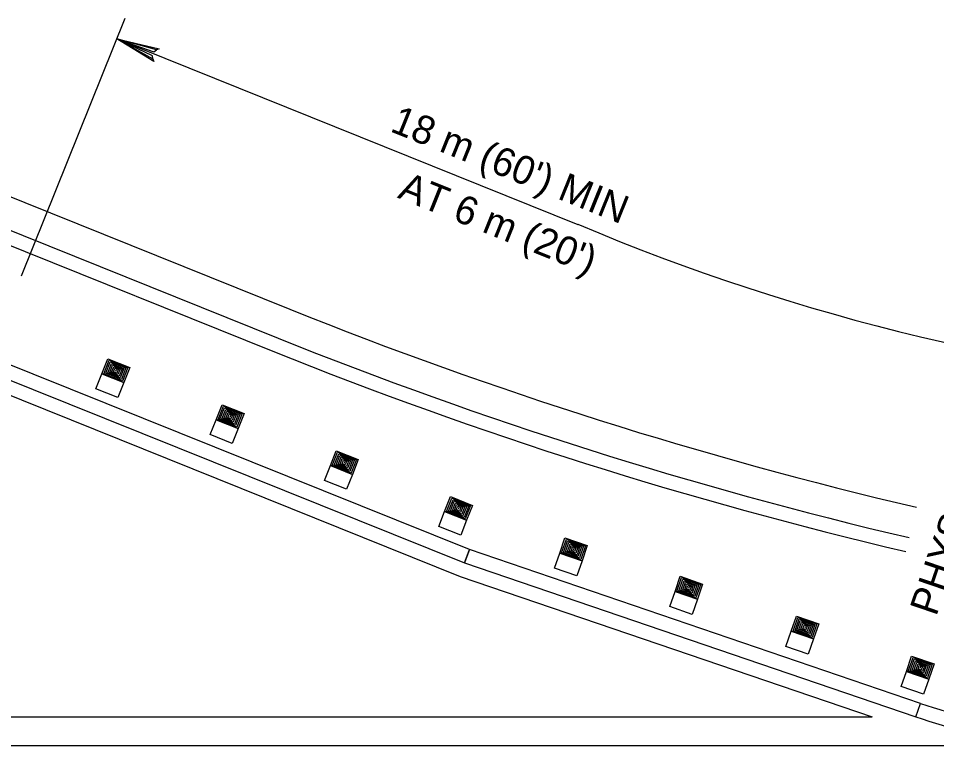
# Model space of a CAD drawing. Extents: x 639362 to 641108, y 298458 to 299646.
# Drawn here: x 639554.2 to 639651.2, y 299503.7 to 299580.5 of the extents above; entities that cross this region are included whole.
import ezdxf

# ---------------------------------------------------------------- set-up
doc = ezdxf.new("R2010")
doc.units = 0
doc.layers.add('2', color=7, linetype='Continuous')

msp = doc.modelspace()

# ---------------------------------------------------------------- linework, layer by layer
at = {"layer": '2'}
for p, q in [((639565.5, 299580.517), (639554.544, 299553.298)), ((639564.624, 299578.342), (639613.294, 299558.754)), ((639520.274, 299575.006), (639582.89, 299549.802)), ((639519.042, 299571.944), (639581.658, 299546.74)), ((639518.53, 299570.534), (639581.098, 299545.349)), ((639601.865, 299524.396), (639514.528, 299559.549)), ((639613.294, 299558.754), (639613.301, 299558.772)), ((639514.014, 299558.139), (639601.342, 299522.99)), ((639513.561, 299556.709), (639600.897, 299521.557)), ((639563.06, 299542.974), (639563.684, 299544.552)), ((639563.261, 299542.98), (639563.825, 299544.405)), ((639563.47, 299543.02), (639563.95, 299544.234)), ((639563.676, 299543.061), (639564.073, 299544.062)), ((639563.684, 299544.552), (639566.008, 299543.632)), ((639563.825, 299544.405), (639565.804, 299543.622)), ((639563.884, 299543.101), (639564.197, 299543.892)), ((639563.95, 299544.234), (639565.601, 299543.581)), ((639564.073, 299544.062), (639565.393, 299543.54)), ((639564.197, 299543.892), (639565.187, 299543.5)), ((639565.383, 299542.054), (639563.06, 299542.974)), ((639565.241, 299542.197), (639563.261, 299542.98)), ((639565.12, 299542.367), (639563.47, 299543.02)), ((639564.996, 299542.538), (639563.676, 299543.061)), ((639564.874, 299542.709), (639563.884, 299543.101)), ((639564.09, 299543.141), (639564.32, 299543.721)), ((639564.75, 299542.88), (639564.09, 299543.141)), ((639564.298, 299543.181), (639564.444, 299543.551)), ((639564.627, 299543.051), (639564.298, 299543.181)), ((639564.32, 299543.721), (639564.979, 299543.46)), ((639564.444, 299543.551), (639564.773, 299543.421)), ((639564.565, 299543.382), (639564.502, 299543.222)), ((639564.773, 299543.421), (639564.627, 299543.051)), ((639564.979, 299543.46), (639564.75, 299542.88)), ((639565.187, 299543.5), (639564.874, 299542.709)), ((639565.393, 299543.54), (639564.996, 299542.538)), ((639565.601, 299543.581), (639565.12, 299542.367)), ((639565.804, 299543.622), (639565.241, 299542.197)), ((639566.008, 299543.632), (639565.383, 299542.054)), ((639575.119, 299538.12), (639575.744, 299539.698)), ((639575.321, 299538.126), (639575.885, 299539.551)), ((639575.53, 299538.166), (639576.01, 299539.38)), ((639575.736, 299538.206), (639576.133, 299539.208)), ((639575.744, 299539.698), (639578.067, 299538.778)), ((639575.885, 299539.551), (639577.864, 299538.768)), ((639575.944, 299538.247), (639576.257, 299539.037)), ((639576.01, 299539.38), (639577.66, 299538.726)), ((639576.133, 299539.208), (639577.453, 299538.686)), ((639576.257, 299539.037), (639577.247, 299538.646)), ((639577.443, 299537.2), (639575.119, 299538.12)), ((639577.3, 299537.343), (639575.321, 299538.126)), ((639577.18, 299537.513), (639575.53, 299538.166)), ((639577.056, 299537.684), (639575.736, 299538.206)), ((639576.934, 299537.855), (639575.944, 299538.247)), ((639576.15, 299538.287), (639576.38, 299538.867)), ((639576.809, 299538.026), (639576.15, 299538.287)), ((639576.357, 299538.327), (639576.504, 299538.697)), ((639576.687, 299538.196), (639576.357, 299538.327)), ((639576.38, 299538.867), (639577.039, 299538.606)), ((639576.504, 299538.697), (639576.833, 299538.567)), ((639576.624, 299538.527), (639576.561, 299538.368)), ((639576.833, 299538.567), (639576.687, 299538.196)), ((639577.039, 299538.606), (639576.809, 299538.026)), ((639577.247, 299538.646), (639576.934, 299537.855)), ((639577.453, 299538.686), (639577.056, 299537.684)), ((639577.66, 299538.726), (639577.18, 299537.513)), ((639577.864, 299538.768), (639577.3, 299537.343)), ((639578.067, 299538.778), (639577.443, 299537.2)), ((639587.179, 299533.265), (639587.804, 299534.843)), ((639587.38, 299533.272), (639587.944, 299534.697)), ((639587.59, 299533.312), (639588.07, 299534.525)), ((639587.796, 299533.352), (639588.192, 299534.354)), ((639587.804, 299534.843), (639590.127, 299533.924)), ((639587.944, 299534.697), (639589.924, 299533.913)), ((639588.004, 299533.393), (639588.316, 299534.183)), ((639588.07, 299534.525), (639589.72, 299533.872)), ((639588.192, 299534.354), (639589.513, 299533.832)), ((639588.316, 299534.183), (639589.306, 299533.791)), ((639589.503, 299532.346), (639587.179, 299533.265)), ((639589.36, 299532.488), (639587.38, 299533.272)), ((639589.24, 299532.659), (639587.59, 299533.312)), ((639589.116, 299532.83), (639587.796, 299533.352)), ((639588.993, 299533.001), (639588.004, 299533.393)), ((639588.21, 299533.433), (639588.439, 299534.013)), ((639588.869, 299533.172), (639588.21, 299533.433)), ((639588.417, 299533.473), (639588.564, 299533.843)), ((639588.746, 299533.342), (639588.417, 299533.473)), ((639588.439, 299534.013), (639589.099, 299533.752)), ((639588.564, 299533.843), (639588.893, 299533.712)), ((639588.684, 299533.673), (639588.621, 299533.514)), ((639588.893, 299533.712), (639588.746, 299533.342)), ((639589.099, 299533.752), (639588.869, 299533.172)), ((639589.306, 299533.791), (639588.993, 299533.001)), ((639589.513, 299533.832), (639589.116, 299532.83)), ((639589.72, 299533.872), (639589.24, 299532.659)), ((639589.924, 299533.913), (639589.36, 299532.488)), ((639590.127, 299533.924), (639589.503, 299532.346)), ((639599.239, 299528.411), (639599.863, 299529.989)), ((639599.44, 299528.418), (639600.004, 299529.843)), ((639599.649, 299528.458), (639600.13, 299529.671)), ((639599.856, 299528.498), (639600.252, 299529.5)), ((639599.863, 299529.989), (639602.187, 299529.069)), ((639600.004, 299529.843), (639601.984, 299529.059)), ((639600.063, 299528.538), (639600.376, 299529.329)), ((639600.13, 299529.671), (639601.78, 299529.018)), ((639600.252, 299529.5), (639601.572, 299528.977)), ((639600.376, 299529.329), (639601.366, 299528.937)), ((639601.562, 299527.492), (639599.239, 299528.411)), ((639601.42, 299527.634), (639599.44, 299528.418)), ((639601.3, 299527.804), (639599.649, 299528.458)), ((639601.176, 299527.975), (639599.856, 299528.498)), ((639601.053, 299528.147), (639600.063, 299528.538)), ((639600.27, 299528.579), (639600.499, 299529.158)), ((639600.929, 299528.318), (639600.27, 299528.579)), ((639600.477, 299528.618), (639600.623, 299528.988)), ((639600.806, 299528.488), (639600.477, 299528.618)), ((639600.499, 299529.158), (639601.159, 299528.897)), ((639600.623, 299528.988), (639600.953, 299528.858)), ((639600.744, 299528.819), (639600.681, 299528.659)), ((639600.953, 299528.858), (639600.806, 299528.488)), ((639601.159, 299528.897), (639600.929, 299528.318)), ((639601.366, 299528.937), (639601.053, 299528.147)), ((639601.572, 299528.977), (639601.176, 299527.975)), ((639601.78, 299529.018), (639601.3, 299527.804)), ((639601.984, 299529.059), (639601.42, 299527.634)), ((639602.187, 299529.069), (639601.562, 299527.492)), ((639611.392, 299524.032), (639611.943, 299525.637)), ((639611.593, 299524.047), (639612.09, 299525.497)), ((639611.8, 299524.097), (639612.223, 299525.332)), ((639611.943, 299525.637), (639614.306, 299524.826)), ((639612.09, 299525.497), (639614.104, 299524.806)), ((639612.223, 299525.332), (639613.902, 299524.755)), ((639601.866, 299524.396), (639601.342, 299522.99)), ((639601.342, 299522.99), (639601.865, 299524.396)), ((639649.463, 299508.153), (639601.866, 299524.396)), ((639612.004, 299524.147), (639612.354, 299525.166)), ((639612.21, 299524.197), (639612.486, 299525.001)), ((639612.354, 299525.166), (639613.697, 299524.705)), ((639612.414, 299524.247), (639612.616, 299524.836)), ((639612.486, 299525.001), (639613.493, 299524.655)), ((639612.616, 299524.836), (639613.287, 299524.606)), ((639612.619, 299524.296), (639612.748, 299524.672)), ((639612.748, 299524.672), (639613.083, 299524.557)), ((639612.877, 299524.509), (639612.821, 299524.346)), ((639613.083, 299524.557), (639612.954, 299524.181)), ((639613.287, 299524.606), (639613.085, 299524.016)), ((639613.493, 299524.655), (639613.216, 299523.851)), ((639613.697, 299524.705), (639613.347, 299523.686)), ((639613.902, 299524.755), (639613.478, 299523.521)), ((639614.104, 299524.806), (639613.606, 299523.356)), ((639614.306, 299524.826), (639613.755, 299523.22)), ((639613.755, 299523.22), (639611.392, 299524.032)), ((639613.606, 299523.356), (639611.593, 299524.047)), ((639613.478, 299523.521), (639611.8, 299524.097)), ((639613.347, 299523.686), (639612.004, 299524.147)), ((639613.216, 299523.851), (639612.21, 299524.197)), ((639613.085, 299524.016), (639612.414, 299524.247)), ((639612.954, 299524.181), (639612.619, 299524.296)), ((639601.342, 299522.99), (639648.969, 299506.737)), ((639600.897, 299521.557), (639644.371, 299506.721)), ((639623.561, 299519.978), (639624.117, 299521.581)), ((639624.117, 299521.581), (639626.478, 299520.762)), ((639623.762, 299519.993), (639624.264, 299521.441)), ((639623.969, 299520.042), (639624.397, 299521.275)), ((639624.174, 299520.091), (639624.527, 299521.109)), ((639624.264, 299521.441), (639626.276, 299520.743)), ((639624.38, 299520.14), (639624.658, 299520.943)), ((639624.397, 299521.275), (639626.074, 299520.693)), ((639624.527, 299521.109), (639625.868, 299520.644)), ((639624.584, 299520.189), (639624.788, 299520.779)), ((639624.658, 299520.943), (639625.664, 299520.595)), ((639624.788, 299520.779), (639625.458, 299520.546)), ((639624.789, 299520.238), (639624.92, 299520.614)), ((639624.92, 299520.614), (639625.254, 299520.498)), ((639625.254, 299520.498), (639625.124, 299520.122)), ((639625.458, 299520.546), (639625.254, 299519.957)), ((639625.664, 299520.595), (639625.385, 299519.791)), ((639625.868, 299520.644), (639625.515, 299519.626)), ((639626.074, 299520.693), (639625.646, 299519.46)), ((639626.276, 299520.743), (639625.774, 299519.295)), ((639626.478, 299520.762), (639625.922, 299519.159)), ((639625.922, 299519.159), (639623.561, 299519.978)), ((639625.774, 299519.295), (639623.762, 299519.993)), ((639625.646, 299519.46), (639623.969, 299520.042)), ((639625.515, 299519.626), (639624.174, 299520.091)), ((639625.385, 299519.791), (639624.38, 299520.14)), ((639625.254, 299519.957), (639624.584, 299520.189)), ((639625.124, 299520.122), (639624.789, 299520.238)), ((639625.047, 299520.45), (639624.991, 299520.288)), ((639635.821, 299515.776), (639636.377, 299517.379)), ((639636.022, 299515.791), (639636.524, 299517.239)), ((639636.229, 299515.84), (639636.656, 299517.073)), ((639636.377, 299517.379), (639638.738, 299516.561)), ((639636.433, 299515.889), (639636.786, 299516.907)), ((639636.524, 299517.239), (639638.535, 299516.541)), ((639636.639, 299515.939), (639636.917, 299516.742)), ((639636.656, 299517.073), (639638.333, 299516.492)), ((639636.786, 299516.907), (639638.128, 299516.442)), ((639636.917, 299516.742), (639637.923, 299516.393)), ((639638.181, 299514.957), (639635.821, 299515.776)), ((639638.033, 299515.094), (639636.022, 299515.791)), ((639637.905, 299515.258), (639636.229, 299515.84)), ((639637.774, 299515.424), (639636.433, 299515.889)), ((639637.645, 299515.59), (639636.639, 299515.939)), ((639636.843, 299515.988), (639637.047, 299516.577)), ((639637.513, 299515.755), (639636.843, 299515.988)), ((639637.047, 299516.577), (639637.718, 299516.344)), ((639637.049, 299516.036), (639637.179, 299516.412)), ((639637.383, 299515.92), (639637.049, 299516.036)), ((639637.179, 299516.412), (639637.514, 299516.296)), ((639637.307, 299516.248), (639637.25, 299516.086)), ((639637.514, 299516.296), (639637.383, 299515.92)), ((639637.718, 299516.344), (639637.513, 299515.755)), ((639637.923, 299516.393), (639637.645, 299515.59)), ((639638.128, 299516.442), (639637.774, 299515.424)), ((639638.333, 299516.492), (639637.905, 299515.258)), ((639638.535, 299516.541), (639638.033, 299515.094)), ((639638.738, 299516.561), (639638.181, 299514.957)), ((639647.986, 299511.532), (639648.542, 299513.136)), ((639648.187, 299511.547), (639648.689, 299512.995)), ((639648.394, 299511.596), (639648.821, 299512.829)), ((639648.542, 299513.136), (639650.902, 299512.317)), ((639648.689, 299512.995), (639650.7, 299512.297)), ((639648.821, 299512.829), (639650.498, 299512.248)), ((639648.598, 299511.645), (639648.951, 299512.663)), ((639648.804, 299511.695), (639649.083, 299512.498)), ((639648.951, 299512.663), (639650.292, 299512.198)), ((639649.008, 299511.744), (639649.213, 299512.333)), ((639649.083, 299512.498), (639650.088, 299512.149)), ((639649.213, 299512.333), (639649.883, 299512.1)), ((639649.214, 299511.792), (639649.344, 299512.168)), ((639649.548, 299511.676), (639649.214, 299511.792)), ((639649.344, 299512.168), (639649.679, 299512.052)), ((639649.472, 299512.004), (639649.416, 299511.842)), ((639649.679, 299512.052), (639649.548, 299511.676)), ((639649.883, 299512.1), (639649.678, 299511.511)), ((639650.088, 299512.149), (639649.809, 299511.346)), ((639650.292, 299512.198), (639649.939, 299511.18)), ((639650.498, 299512.248), (639650.071, 299511.014)), ((639650.7, 299512.297), (639650.198, 299510.85)), ((639650.902, 299512.317), (639650.346, 299510.713)), ((639650.346, 299510.713), (639647.986, 299511.532)), ((639650.198, 299510.85), (639648.187, 299511.547)), ((639650.071, 299511.014), (639648.394, 299511.596)), ((639649.939, 299511.18), (639648.598, 299511.645)), ((639649.809, 299511.346), (639648.804, 299511.695)), ((639649.678, 299511.511), (639649.008, 299511.744)), ((639648.969, 299506.737), (639649.463, 299508.153)), ((639511.242, 299506.721), (639644.371, 299506.721)), ((639511.242, 299503.694), (639660.336, 299503.694))]:
    msp.add_line(p, q, dxfattribs=at)
msp.add_lwpolyline([(639568.428, 299576.226), (639568.391, 299576.575), (639564.624, 299578.342), (639568.428, 299576.226), (639568.56, 299575.967), (639564.624, 299578.342), (639568.555, 299576.982), (639568.811, 299577.209), (639564.624, 299578.342), (639569.101, 299577.314), (639568.811, 299577.209)], dxfattribs=at)
for points in [[(639563.06, 299542.974), (639565.383, 299542.054), (639564.759, 299540.476), (639562.435, 299541.396)], [(639575.119, 299538.119), (639577.443, 299537.2), (639576.818, 299535.622), (639574.495, 299536.541)], [(639587.179, 299533.265), (639589.503, 299532.346), (639588.878, 299530.768), (639586.555, 299531.687)], [(639599.239, 299528.411), (639601.562, 299527.491), (639600.938, 299525.913), (639598.614, 299526.833)], [(639611.392, 299524.032), (639613.755, 299523.22), (639613.204, 299521.615), (639610.841, 299522.426)], [(639623.561, 299519.978), (639625.922, 299519.159), (639625.366, 299517.555), (639623.005, 299518.374)], [(639635.821, 299515.776), (639638.181, 299514.957), (639637.625, 299513.354), (639635.264, 299514.173)], [(639647.986, 299511.532), (639650.346, 299510.713), (639649.79, 299509.11), (639647.43, 299509.928)]]:
    msp.add_lwpolyline(points, close=True, dxfattribs=at)
for centre, radius, start, end in [((639702.31, 299768.715), 228.032, 247.02471, 266.18309), ((639753.05, 299972.54), 455.7, 248.07429, 256.80815), ((639753.05, 299972.54), 459, 248.07429, 256.80425), ((639753.05, 299972.54), 460.5, 248.07429, 256.80425), ((639678.554, 299595.485), 92.049, 251.57665, 265.76929), ((639679.825, 299599.258), 97.531, 251.55634, 258.47319)]:
    msp.add_arc(centre, radius, start, end, dxfattribs=at)

# ---------------------------------------------------------------- texts
for s, rotation, p in [("18 m (60') MIN", 338.07675, (639593.375, 299568.616)), ("AT 6 m (20')", 338.07675, (639594.175, 299561.598)), ('PHYSICAL', 71.15724, (639651.128, 299517.267))]:
    msp.add_text(s, height=3, rotation=rotation, dxfattribs=at).set_placement(p)

doc.saveas('drawing.dxf')
